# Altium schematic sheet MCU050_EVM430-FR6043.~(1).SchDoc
size 431 x 279 mm; Date: Not shown in title block; ApprovedBy: Not shown in title block; CheckedBy: Not shown in title block; Author: Not shown in title block; CompanyName: Not shown in title block; Engineer: Not shown in title block; Organization: Not shown in title block; Address1: Not shown in title block; Address2: Not shown in title block; Address3: Not shown in title block; Address4: Not shown in title block; DocumentNumber: 1; Revision: Use project parameter SCH_Rev; SheetNumber: 1; SheetTotal: 7; PageSetup: Record=PageOptions¦CenterHorizontal=True¦CenterVertical=True¦PrintScale=1.00¦XCorrection=1.00¦YCorrection=1.00¦PrintKind=0¦BorderSize=5000000¦LeftOffset=0¦BottomOffset=0¦Orientation=2¦PaperLength=1000¦PaperWidth=1000¦Scale=100¦PaperSource=15¦PrintQuality=600¦MediaType=1¦DitherType=10¦PaperKind=Letter¦PrintScaleMode=1
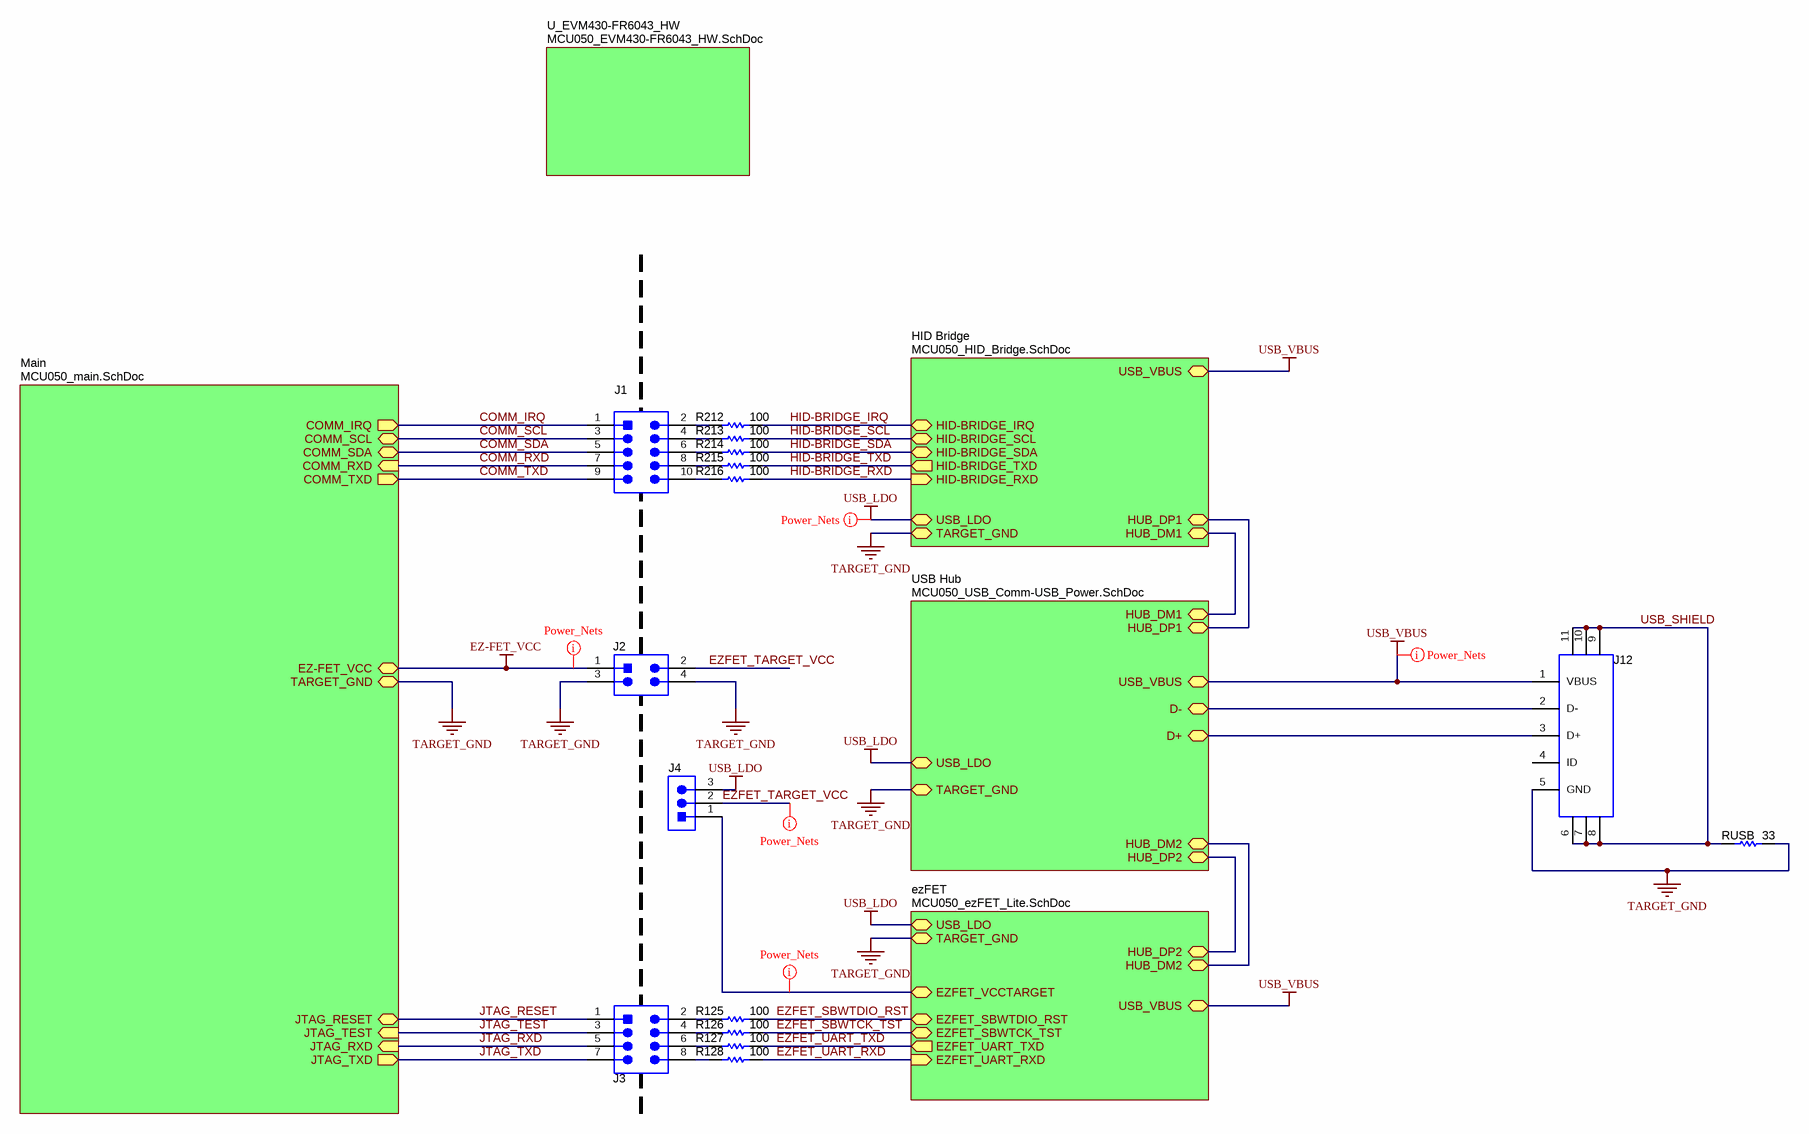
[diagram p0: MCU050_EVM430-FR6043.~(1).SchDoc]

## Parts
J1  TSW-105-07-G-D  [TSW-105-07-G-D]  (value not drawn)
J2  PBC02DAAN  [Sullins_PxC02DAAN]  (value not drawn)
J3  PEC04DAAN  [CONN_PEC04DAAN]  (value not drawn)
J4  61300311121  [WURTH_61300311121]  (value not drawn)
J12  1051640001  [Molex_1051640001]  (value not drawn)
R125  ValueDisplayed: 100  [0402S]  (hidden comment: CRCW0402100RJNED)
R126  ValueDisplayed: 100  [0402S]  (hidden comment: CRCW0402100RJNED)
R127  ValueDisplayed: 100  [0402S]  (hidden comment: CRCW0402100RJNED)
R128  ValueDisplayed: 100  [0402S]  (hidden comment: CRCW0402100RJNED)
R212  ValueDisplayed: 100  [0402S]  (hidden comment: CRCW0402100RJNED)
R213  ValueDisplayed: 100  [0402S]  (hidden comment: CRCW0402100RJNED)
R214  ValueDisplayed: 100  [0402S]  (hidden comment: CRCW0402100RJNED)
R215  ValueDisplayed: 100  [0402S]  (hidden comment: CRCW0402100RJNED)
R216  ValueDisplayed: 100  [0402S]  (hidden comment: CRCW0402100RJNED)
RUSB  value 33  [0402S]  (hidden comment: CRCW040233R0JNED)

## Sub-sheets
ezFET = MCU050_ezFET_Lite.SchDoc: EZFET_SBWTDIO_RST (bidir), EZFET_SBWTCK_TST (bidir), EZFET_UART_TXD (out), EZFET_UART_RXD (in), HUB_DP2 (bidir), HUB_DM2 (bidir), USB_VBUS, TARGET_GND, USB_LDO, EZFET_VCCTARGET
HID Bridge = MCU050_HID_Bridge.SchDoc: HID-BRIDGE_TXD (out), HID-BRIDGE_RXD (in), HID-BRIDGE_SCL (bidir), HID-BRIDGE_SDA (bidir), HID-BRIDGE_IRQ (bidir), USB_VBUS, USB_LDO, TARGET_GND, HUB_DM1 (bidir), HUB_DP1 (bidir)
Main = MCU050_main.SchDoc: COMM_RXD (in), COMM_TXD (out), COMM_SCL (bidir), COMM_SDA (bidir), EZ-FET_VCC, TARGET_GND, COMM_IRQ (out), JTAG_TXD (out), JTAG_RXD (in), JTAG_TEST (in), JTAG_RESET (bidir)
U_EVM430-FR6043_HW = MCU050_EVM430-FR6043_HW.SchDoc: no entries
USB Hub = MCU050_USB_Comm-USB_Power.SchDoc: HUB_DM1 (bidir), HUB_DP1 (bidir), HUB_DP2 (bidir), HUB_DM2 (bidir), USB_LDO, USB_VBUS, D- (bidir), D+ (bidir), TARGET_GND

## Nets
EZ-FET_VCC: J2.1 ; sheet Main/EZ-FET_VCC
TARGET_GND: J2.3 J2.4 J12.5(GND) RUSB.1 ; sheet Main/TARGET_GND, sheet HID Bridge/TARGET_GND, sheet USB Hub/TARGET_GND, sheet ezFET/TARGET_GND
USB_LDO: J4.3 ; sheet HID Bridge/USB_LDO, sheet USB Hub/USB_LDO, sheet ezFET/USB_LDO
USB_VBUS: J12.1(VBUS) ; sheet HID Bridge/USB_VBUS, sheet USB Hub/USB_VBUS, sheet ezFET/USB_VBUS
COMM_IRQ: J1.1 ; sheet Main/COMM_IRQ
COMM_RXD: J1.7 ; sheet Main/COMM_RXD
COMM_SCL: J1.3 ; sheet Main/COMM_SCL
COMM_SDA: J1.5 ; sheet Main/COMM_SDA
COMM_TXD: J1.9 ; sheet Main/COMM_TXD
EZFET_SBWTCK_TST: R126.1 ; sheet ezFET/EZFET_SBWTCK_TST
EZFET_SBWTDIO_RST: R125.1 ; sheet ezFET/EZFET_SBWTDIO_RST
EZFET_TARGET_VCC: J2.2 J4.2
EZFET_UART_RXD: R128.1 ; sheet ezFET/EZFET_UART_RXD
EZFET_UART_TXD: R127.1 ; sheet ezFET/EZFET_UART_TXD
HID-BRIDGE_IRQ: R212.1 ; sheet HID Bridge/HID-BRIDGE_IRQ
HID-BRIDGE_RXD: R216.1 ; sheet HID Bridge/HID-BRIDGE_RXD
HID-BRIDGE_SCL: R213.1 ; sheet HID Bridge/HID-BRIDGE_SCL
HID-BRIDGE_SDA: R214.1 ; sheet HID Bridge/HID-BRIDGE_SDA
HID-BRIDGE_TXD: R215.1 ; sheet HID Bridge/HID-BRIDGE_TXD
JTAG_RESET: J3.1 ; sheet Main/JTAG_RESET
JTAG_RXD: J3.5 ; sheet Main/JTAG_RXD
JTAG_TEST: J3.3 ; sheet Main/JTAG_TEST
JTAG_TXD: J3.7 ; sheet Main/JTAG_TXD
USB_SHIELD: J12.6 J12.7 J12.8 J12.9 J12.10 J12.11 RUSB.2
NetJ1_2: J1.2 R212.2
NetJ1_4: J1.4 R213.2
NetJ1_6: J1.6 R214.2
NetJ1_8: J1.8 R215.2
NetJ1_10: J1.10 R216.2
NetJ3_2: J3.2 R125.2
NetJ3_4: J3.4 R126.2
NetJ3_6: J3.6 R127.2
NetJ3_8: J3.8 R128.2
NetJ4_1: J4.1 ; sheet ezFET/EZFET_VCCTARGET
NetJ12_2: J12.2(D-) ; sheet USB Hub/D-
NetJ12_3: J12.3(D+) ; sheet USB Hub/D+
(unnamed): sheet HID Bridge/HUB_DM1, sheet USB Hub/HUB_DM1
(unnamed): sheet HID Bridge/HUB_DP1, sheet USB Hub/HUB_DP1  [a separate net that carries the same name]
(unnamed): sheet USB Hub/HUB_DP2, sheet ezFET/HUB_DP2  [a separate net that carries the same name]
(unnamed): sheet USB Hub/HUB_DM2, sheet ezFET/HUB_DM2  [a separate net that carries the same name]

Not connected (* = marked no-connect by the designer): J12 4(ID)

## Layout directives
net class Power_Nets: EZ-FET_VCC, EZFET_TARGET_VCC, NetJ4_1, USB_LDO, USB_VBUS

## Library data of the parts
J1 = TSW-105-07-G-D: Header, 100mil, 5x2, Gold, TH; Manufacturer: Samtec; SymbolCreator: a0412235; Pitch_mm: 2.54; Gender: Male; Shrouded: N; Row_Count: 2; Current_A: 6.3; Voltage_V: 550; Cert_CSA: Y; Green_Lifecycle: Active; Green_REACh: Passed
J2 = PBC02DAAN: Header, 2.54mm, 2x2, Gold, TH; Manufacturer: Sullins Connector Solutions; SymbolCreator: a0412235; Pitch_mm: 2.54; Gender: Male; Shrouded: N; Row_Count: 2; Current_A: 3; Voltage_V: 1800; Cert_UL: Y
J3 = PEC04DAAN: Header, 100mil, 4x2, Tin, TH; Manufacturer: Sullins Connector Solutions; SymbolCreator: a0411947; Pitch_mm: 2.54; Gender: Male; Shrouded: N; Row_Count: 2; Current_A: 3; Voltage_V: 1800; Cert_UL: Y; Green_Lifecycle: Not Set; Green_REACh: Incomplete
J4 = 61300311121: Header, 2.54 mm, 3x1, Gold, TH; Manufacturer: Wurth Elektronik; SymbolCreator: a0799628; Green_Lifecycle: Active; Green_REACh: Passed
J12 = 1051640001: Receptacle, USB 2.0, Micro B, 5 Position, R/A, SMT; Manufacturer: Molex; SymbolCreator: a0411947; Pitch_mm: 0.65; Gender: Female; ContactFinish: Gold; Current_A: 1.8; Voltage_V: 30; Cert_UL: Y
R125-R128 R212-R216 = CRCW0402100RJNED: RES, 100, 5%, 0.063 W, 0402; Manufacturer: Vishay-Dale; CompType: Resistor; Value: 100; Value_Code: 100R; Tolerance_%: 5; Power_W: 0.063; Value2: 0.063W; VDC_V: 50; TempCo: 200 ppm/C; EIA_Code: E24; U/M: EA; AEC Category: Q200
RUSB = CRCW040233R0JNED: RES, 33 ohm, 5%, 0.063W, 0402; Manufacturer: Vishay-Dale; CompType: Resistor; Value_Code: 33R0; Tolerance_%: 5; Power_W: 0.063; VDC_V: 50; TempCo: 200 ppm/C; EIA_Code: E24; U/M: EA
